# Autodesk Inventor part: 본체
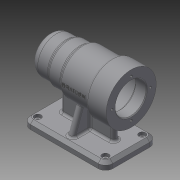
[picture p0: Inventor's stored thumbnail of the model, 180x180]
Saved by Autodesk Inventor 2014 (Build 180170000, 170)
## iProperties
Created: 2016-06
Part Number: 본체
Material: 일반
Document SubType Name: Modeling
Designer: L6
Density: 1 g/cm^3
Appearance: 기본값
Author: L6
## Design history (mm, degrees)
sketch "스케치1"
  geometry: L1 (-56, -35)-(56, -35); L2 (56, -35)-(56, 35); L3 (56, 35)-(-56, 35); L4 (-56, 35)-(-56, -35); L5 (-56, -35)-(56, 35); L6 (56, -35)-(-56, 35); 1 further point
  constraints: 12 end point, 2 midpoint, 2 parallel, 1 horizontal, 1 perpendicular
  dimensions: "d0" = 112 distance of L2.end L3.end; "d1" = 70 distance of L1.end L2.end
extrude "돌출1" new body sketch "스케치1" distance "d2" = 10; taper "d3" = 0 deg
sketch "스케치2"
  geometry: L1 (-36, 4)-(36, 4); L2 (36, 4)-(36, -4); L3 (36, -4)-(-36, -4); L4 (-36, -4)-(-36, 4); L5 (-36, 4)-(36, -4); L6 (36, 4)-(-36, -4); 1 further point
  constraints: 12 end point, 2 midpoint, 2 parallel, 1 horizontal, 1 perpendicular
  dimensions: "d4" = 72 distance of L1.start L1.end; "d5" = 8 distance of L1.end L2.end
extrude "돌출2" join sketch "스케치2" distance "d6" = 60; taper "d7" = 0 deg
sketch "스케치3"
  geometry: L1 (-35, 0)-(-35, 10) reference; L2 (35, 0)-(35, 10) reference; L3 (-28, 10)-(28, 10); L4 (28, 10)-(6.162, 70); L5 (6.162, 70)-(-6.162, 70); L6 (-6.162, 70)-(-28, 10); L7 (35, 0)-(-35, 0) reference; L8 (35, 10)-(-35, 10) reference; 1 further point
  constraints: 8 end point, 1 parallel, 1 perpendicular
  dimensions: "d8" = 7 distance from line of L1 L3.start; "d9" = 7 distance from line of L3.end L2; "d10" = 10 distance between parallel lines of L7 L3; "d11" = 110 deg angle of L8 L6; "d12" = 110 deg angle of L8 L4; "d13" = 60 distance between parallel lines of L3 L5
extrude "돌출3" join sketch "스케치3" stored distance "d14" = 8; taper "d15" = 0 deg
sketch "스케치4"
  geometry: L1 (0, 0)-(-10, 0) reference; L2 (0, 35)-(-70, 35); C1 r 34 at (-70, 35)
  constraints: 2 end point, 1 centre point, 1 coincident, 1 parallel
  dimensions: "d16" = 70 distance of L2.start L2.end; "d17" = 68 diameter of C1
extrude "돌출4" join sketch "스케치4" distance "d18" = 28; taper "d19" = 0 deg
sketch "스케치5"
  geometry: C1 r 30 at (70, 35); A1 r 34 centre (70, 35) between (36.236, 31) and (36.236, 39) reference; 1 further point
  constraints: 1 centre point, 1 coincident
  dimensions: "d20" = 60 diameter of C1
extrude "돌출5" join sketch "스케치5" distance "d21" = 39; taper "d22" = 0 deg
sketch "스케치6"
  geometry: C1 r 27 at (70, 35); A1 r 30 centre (70, 35) between (40.268, 31) and (40.268, 39) reference; 1 further point
  constraints: 1 centre point, 1 coincident
  dimensions: "d23" = 54 diameter of C1
extrude "돌출6" join sketch "스케치6" distance "d24" = 20; taper "d25" = 0 deg
sketch "스케치7"
  geometry: C1 r 25 at (70, 35); A1 r 27 centre (70, 35) between (43.298, 31) and (43.298, 39) reference; 1 further point
  constraints: 1 centre point, 1 coincident
  dimensions: "d26" = 50 diameter of C1
extrude "돌출7" join sketch "스케치7" distance "d27" = 25; taper "d28" = 0 deg
fillet "모깎기1" dims "d29" = 10
sketch "스케치8"
  geometry: C1 r 34 at (0, 0) reference; C2 r 21 at (0, 0); 1 further point
  constraints: 1 centre point, 1 coincident
  dimensions: "d30" = 42 diameter of C2
extrude "돌출8" cut sketch "스케치8" distance "d31" = 15; taper "d32" = 0 deg
sketch "스케치9"
  geometry: C1 r 21 at (0, 0) reference; C2 r 24 at (0, 0); 1 further point
  constraints: 1 centre point, 1 coincident
  dimensions: "d33" = 48 diameter of C2
extrude "돌출9" cut sketch "스케치9" distance "d34" = 54; taper "d35" = 0 deg
sketch "스케치10"
  geometry: C1 r 24 at (0, 0) reference; C2 r 21 at (0, 0); 1 further point
  constraints: 1 centre point, 1 coincident
  dimensions: "d36" = 42 diameter of C2
extrude "돌출10" cut sketch "스케치10" distance "d37" = 12; taper "d38" = 0 deg
sketch "스케치11"
  geometry: C1 r 21 at (0, 0) reference; C2 r 17.5 at (0, 0); 1 further point
  constraints: 1 centre point, 1 coincident
  dimensions: "d39" = 35 diameter of C2
extrude "돌출11" cut sketch "스케치11" distance "d40" = 18; taper "d41" = 0 deg
sketch "스케치12"
  geometry: C1 r 17.5 at (0, 0) reference; C2 r 16 at (0, 0); 1 further point
  constraints: 1 centre point, 1 coincident
  dimensions: "d42" = 32 diameter of C2
extrude "돌출12" cut sketch "스케치12" distance "d43" = 4; taper "d44" = 0 deg
sketch "스케치13"
  geometry: C1 r 16 at (0, 0) reference; C2 r 10.5 at (0, 0); 1 further point
  constraints: 1 centre point, 1 coincident
  dimensions: "d45" = 21 diameter of C2
extrude "돌출13" cut sketch "스케치13" distance "d46" = 3; taper "d47" = 0 deg
fillet "모깎기2" dims "d48" = 10
sketch "스케치15"
  geometry: A1 r 10 centre (-46, 25) between (-46, 35) and (-56, 25) reference; A2 r 10 centre (-46, -25) between (-56, -25) and (-46, -35) reference; A3 r 10 centre (46, -25) between (46, -35) and (56, -25) reference; A4 r 10 centre (46, 25) between (56, 25) and (46, 35) reference; 1 further point
hole "구멍1" sketch "스케치15" at (-46, -25), (46, -25), (46, 25), (-46, 25) diameter "d49" = 5; stored, may be unused: countersink angle "d53" = 90 deg, drill point angle "d55" = 118 deg; dims "d50" = 6, "d51" = 9, "d52" = 4, "d54" = 8
chamfer "모따기1" distance "d56" = 1; stored, may be unused: second distance "d57" = 2, angle "d58" = 45 deg
fillet "모깎기3" dims "d59" = 3
fillet "모깎기4" dims "d60" = 0.3
fillet "모깎기5" dims "d61" = 3
sketch "스케치16"
  geometry: L1 (0, 0)-(0, 26); C1 r 22 at (0, 0) reference; 2 further points
  constraints: 2 end point, 1 coincident, 1 vertical
  dimensions: "d62" = 26 distance of L1.start L1.end
hole "구멍2" sketch "스케치16" at (0, 26) diameter "d63" = 3.242; stored, may be unused: countersink angle "d67" = 90 deg, drill point angle "d69" = 118 deg; dims "d64" = 8, "d65" = 9, "d66" = 4, "d68" = 11
chamfer "모따기2" distance "d73" = 4; stored, may be unused: second distance "d74" = 2, angle "d75" = 45 deg
fillet "모깎기6" dims "d76" = 3
fillet "모깎기7" dims "d77" = 3
fillet "모깎기8" dims "d78" = 3
fillet "모깎기9" dims "d79" = 4
fillet "모깎기10" dims "d80" = 3
fillet "모깎기11" dims "d81" = 3
fillet "모깎기12" dims "d82" = 3
node "작업 평면1"
sketch "스케치17"
  geometry: L1 (56, 104)-(56, 36) reference; 2 further points
  constraints: 1 other
  dimensions: "d84" = 48 distance from line of L1 point (8, 70); "d85" = 70 vertical distance of point (0, 0) point (8, 70)
feature "엠보싱1" sketch "스케치17" dims "d86" = 0.5, "d87" = 0
fillet "모깎기13" dims "d90" = 3
node "솔리드1"
pattern_circular "원형 패턴1" dims angle "d71" = 360 deg
other parameters: "d83" = -42.5
